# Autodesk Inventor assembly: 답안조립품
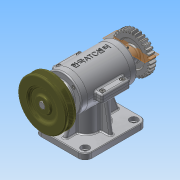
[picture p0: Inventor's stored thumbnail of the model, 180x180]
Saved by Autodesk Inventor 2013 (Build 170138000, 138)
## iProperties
Created: 2015-09
Part Number: 답안조립품
Document SubType Name: Assembly
Designer: Administrator
Author: Administrator
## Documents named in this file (17)
- C:\Users\Administrator\Desktop\350908V1027\답안조립품.iam
- C:\Users\Administrator\Desktop\350908V1027\본체.ipt
- C:\Users\Administrator\Desktop\350908V1027\M3x0.5x8.ipt
- C:\Users\Administrator\Desktop\350908V1027\M4x0.5x14.ipt
- C:\Users\Administrator\Desktop\350908V1027\V-벨트풀리.ipt
- C:\Users\Administrator\Desktop\350908V1027\가변스프링.ipt
- C:\Users\Administrator\Desktop\350908V1027\뒤커버.ipt
- C:\Users\Administrator\Desktop\350908V1027\멈춤나사.ipt
- C:\Users\Administrator\Desktop\350908V1027\베어링 6201.ipt
- C:\Users\Administrator\Desktop\350908V1027\베어링 6202.ipt
- C:\Users\Administrator\Desktop\350908V1027\본체 커버.ipt
- C:\Users\Administrator\Desktop\350908V1027\스퍼기어.ipt
- C:\Users\Administrator\Desktop\350908V1027\슬라이드.ipt
- C:\Users\Administrator\Desktop\350908V1027\앞커버.ipt
- C:\Users\Administrator\Desktop\350908V1027\오일실.ipt
- C:\Users\Administrator\Desktop\350908V1027\키4x4.ipt
- C:\Users\Administrator\Desktop\350908V1027\편심축.ipt
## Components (14 placed, 4 different names)
1. M4x0.5x14:1
2. V-벨트풀리:1 — 플러쉬:2, 각도:1
3. 가변스프링:1
4. M4x0.5x14:2
5. M4x0.5x14:3
6. M4x0.5x14:4
7. M3x0.5x8:1
8. M3x0.5x8:3
9. M3x0.5x8:4
10. M3x0.5x8:5
11. M3x0.5x8:2
12. M3x0.5x8:6
13. M3x0.5x8:7
14. M3x0.5x8:8
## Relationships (2: Flush 1, Angle 1)
- 플러쉬:2 [Flush]: V-벨트풀리:1
- 각도:1 [Angle]: V-벨트풀리:1
